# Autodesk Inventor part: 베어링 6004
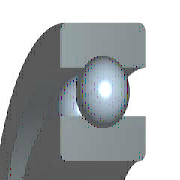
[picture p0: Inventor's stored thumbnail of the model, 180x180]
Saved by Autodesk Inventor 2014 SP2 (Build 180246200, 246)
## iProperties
Created: 2012-02
Part Number: 베어링 6004
Material: 강철, 연강
Description: 깊은 그루브 볼 베어링
Document SubType Name: Modeling
Standard: KS B 2023
Designer: mduedu
Standards Organization: KS
Language: ko-KR
Size Designation: 6004 - 20 x 42 x 12
Categories: <MemberInstance><Categories><Category DisplayName="샤프트 부품" InternalName="7f7aeb1f-a693-4053-b835-cee3144e0d98" Mnemonic="SHFT"><Category DisplayName="베어링" Inter
Density: 1 g/cm^3
Appearance: 노란색
IsCustomPart: 1
Author: mduedu
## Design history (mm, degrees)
sketch "스케치" dims "d0" = 5.72 (= -0.26 x WD + 0.26 x BD)
  geometry: L1 (3.14, 15.5)-(8.86, 15.5); L2 (6, 15.5)-(6, 12.64); L3 (6, 15.5)-(6, 18.36); L4 (3.875, 13.586)-(0, 13.586); L5 (0, 10)-(12, 10); L6 (3.875, 17.414)-(0, 17.414); L7 (0, 21)-(12, 21); L8 (12, 10)-(12, 13.586); L9 (8.125, 13.586)-(12, 13.586); L10 (8.125, 17.414)-(12, 17.414); L11 (12, 21)-(12, 17.414); L12 (-1.4, 0)-(8.4, 0) reference; L13 (0, -0.3)-(0, 5.3) reference
  constraints: 22 end point, 4 point on line, 2 collinear, 2 perpendicular, 2 symmetric about line, 1 midpoint, 1 parallel, 14 other
  dimensions: "d9" = 20 diameter of L5 L12 (= WD); "d11" = 42 diameter of L7 L12 (= BD); "d12" = 12 distance between parallel lines of L8 L13 (= KB); "d13" = 27.172 diameter of L9 L12 (= 0.326 x BD + 0.674 x WD)
revolve "본체" stored, may be unused: angle "d6" = 90 deg
revolve "볼" stored, may be unused: angle "d7" = 90 deg
pattern_circular "IDS_ARRAYBALL[SIMPL:T]" dims angle "d3" = 360 deg
body "Solid1"
fillet "모깎기1" dims "d1" = 0.6 (= KRS)
other parameters: "WD" = 20 [user parameter; used in 5 equation terms], "BD" = 42 [user parameter; used in 5 equation terms], "KB" = 12 [user parameter; used in 1 equation term], "KRS" = 0.6 [user parameter; used in 1 equation term], "d4" = 0, "d5" = 0, "d8" = 0, "d14" = 0, "d15" = 0, "BBA" = 0 [user parameter], "BC0" = 5000000 [user parameter], "BC" = 9360000 [user parameter], "BR" = 21 (= 0.5 x BD) [user parameter]
